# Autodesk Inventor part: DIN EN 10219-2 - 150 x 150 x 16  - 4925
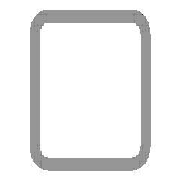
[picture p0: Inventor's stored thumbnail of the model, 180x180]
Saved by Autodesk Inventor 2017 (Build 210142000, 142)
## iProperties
IsCustomPart: 1
Created: 2017-11
Part Number: DIN EN 10219-2 - 150 x 150 x 16  - 4925
Material: Steel, Mild
Description: Cold formed welded structural hollow sections of non-alloy and fine grain structural steel
Document SubType Name: Modeling
Standard: DIN
Designer: iusti
Standard Revision: 2006-07
Standards Organization: DIN
Language: en-US
Size Designation: 150 x 150 x 16
Categories: <MemberInstance><Categories><Category DisplayName="Structural Shapes" InternalName="089c4875-fa83-4c05-b084-43b9cc11f5ed" Mnemonic="GRDR"><CategoryParameter Dis
Stock Number: 150 x 150 x 16
Density: 7.85 g/cm^3
Appearance: Semi-Polished
Mass: 289079 g
Surface Area: 46181.3 cm^2
Volume: 36825.4 cm^3
_CCFamilyMember: 76
_CCFamilyDisplayName: DIN EN 10219-2 (Square Hollow Section - Cold Formed) - Cold formed welded structural hollow sections of non-alloy and fine grain structural steel
_FrameMemberDoc: Frame Member File
_Version: 15.0.0
_GetPNFromCC: 1
G_L: 4925.000 mm
G_W: 150.000 mm
G_H: 150.000 mm
+64C0199E-E4A6-42EE-BAB6-C57CBAF8A212+CUTDETAIL1: Cut
Author: iusti
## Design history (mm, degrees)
node "Start plane"
node "End plane"
sketch "Sketch"
  geometry: L1 (-75, -27)-(-75, 27); L2 (-27, 75)-(27, 75); L3 (75, 27)-(75, -27); L4 (27, -75)-(-27, -75); L5 (-27, 59)-(27, 59); L6 (59, 27)-(59, -27); L7 (27, -59)-(-27, -59); L8 (-59, -27)-(-59, 27); L9 (0, 118.918)-(0, -118.918) reference; L10 (-118.918, 0)-(118.918, 0) reference; A1 r 48 centre (-27, -27) between (-75, -27) and (-27, -75); A2 r 48 centre (-27, 27) between (-27, 75) and (-75, 27); A3 r 48 centre (27, 27) between (75, 27) and (27, 75); A4 r 48 centre (27, -27) between (27, -75) and (75, -27); A5 r 32 centre (-27, 27) between (-27, 59) and (-59, 27); A6 r 32 centre (27, 27) between (59, 27) and (27, 59); A7 r 32 centre (27, -27) between (27, -59) and (59, -27); A8 r 32 centre (-27, -27) between (-59, -27) and (-27, -59)
  constraints: 16 end point, 16 point on circle, 8 centre point, 8 tangent, 4 parallel, 3 equal radius, 2 perpendicular, 7 other
  dimensions: "d7" = 48 radius of A1 (= G_IR); "d10" = 150 distance between parallel lines of L2 L4 (= G_H); "d11" = 150 distance between parallel lines of L1 L3 (= G_W); "d12" = 16 distance between parallel lines of L3 L6 (= G_T); "d15" = 75 distance between parallel lines of L2 L10 (= 0.5 x d10); "d16" = 75 distance between parallel lines of L9 L3 (= 0.5 x d11)
extrude "Body" new body sketch "Sketch" stored distance "d3" = 4925 (= G_L); taper "d4" = 0 deg
node "Driven Length"
  sketch "Sketch3"
    geometry: L1 (0, 0)-(10, 0) reference
    constraints: 2 end point, 1 horizontal
  workplane "Work Plane3"
  sketch "Sketch4"
    geometry: L1 (-2, 0)-(12, 0) reference; L2 (-2, 4925)-(12, 4925) reference
    dimensions: "d18" = 4925 distance between parallel lines of L1 L2 (derived)
workplane "Work Plane4"
split "Split1"
body "Solid1"
other parameters: "G_W" = 150 [user parameter; used in 1 equation term], "G_H" = 150 [user parameter; used in 1 equation term], "G_T" = 16 [user parameter; used in 1 equation term], "G_IR" = 48 [user parameter; used in 1 equation term], "G_L" = 4925 (= d18) [user parameter; used in 1 equation term], "G_OFFSET_START" = 0 [user parameter; used in 1 equation term], "G_OFFSET_END" = -75 [user parameter; used in 1 equation term], "d13" = 0 (computed from G_OFFSET_START), "d14" = 4925 (= G_OFFSET_END + B_L), "d17" = 90 deg
